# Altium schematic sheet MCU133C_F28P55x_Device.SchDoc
size 431 x 279 mm; Date: Not shown in title block; ApprovedBy: Not shown in title block; CheckedBy: Not shown in title block; Author: Not shown in title block; CompanyName: Not shown in title block; Engineer: Not shown in title block; Organization: Not shown in title block; Address1: Not shown in title block; Address2: Not shown in title block; Address3: Not shown in title block; Address4: Not shown in title block; DocumentNumber: 4; Revision: Use project parameter SCH_Rev; SheetNumber: 4; SheetTotal: 8; PageSetup: Record=PageOptions¦CenterHorizontal=True¦CenterVertical=True¦PrintScale=1.00¦XCorrection=1.00¦YCorrection=1.00¦PrintKind=0¦BorderSize=5000000¦LeftOffset=0¦BottomOffset=0¦Orientation=2¦PaperLength=1000¦PaperWidth=1000¦Scale=100¦PaperSource=15¦PrintQuality=600¦MediaType=1¦DitherType=10¦PaperKind=Letter¦PrintScaleMode=1
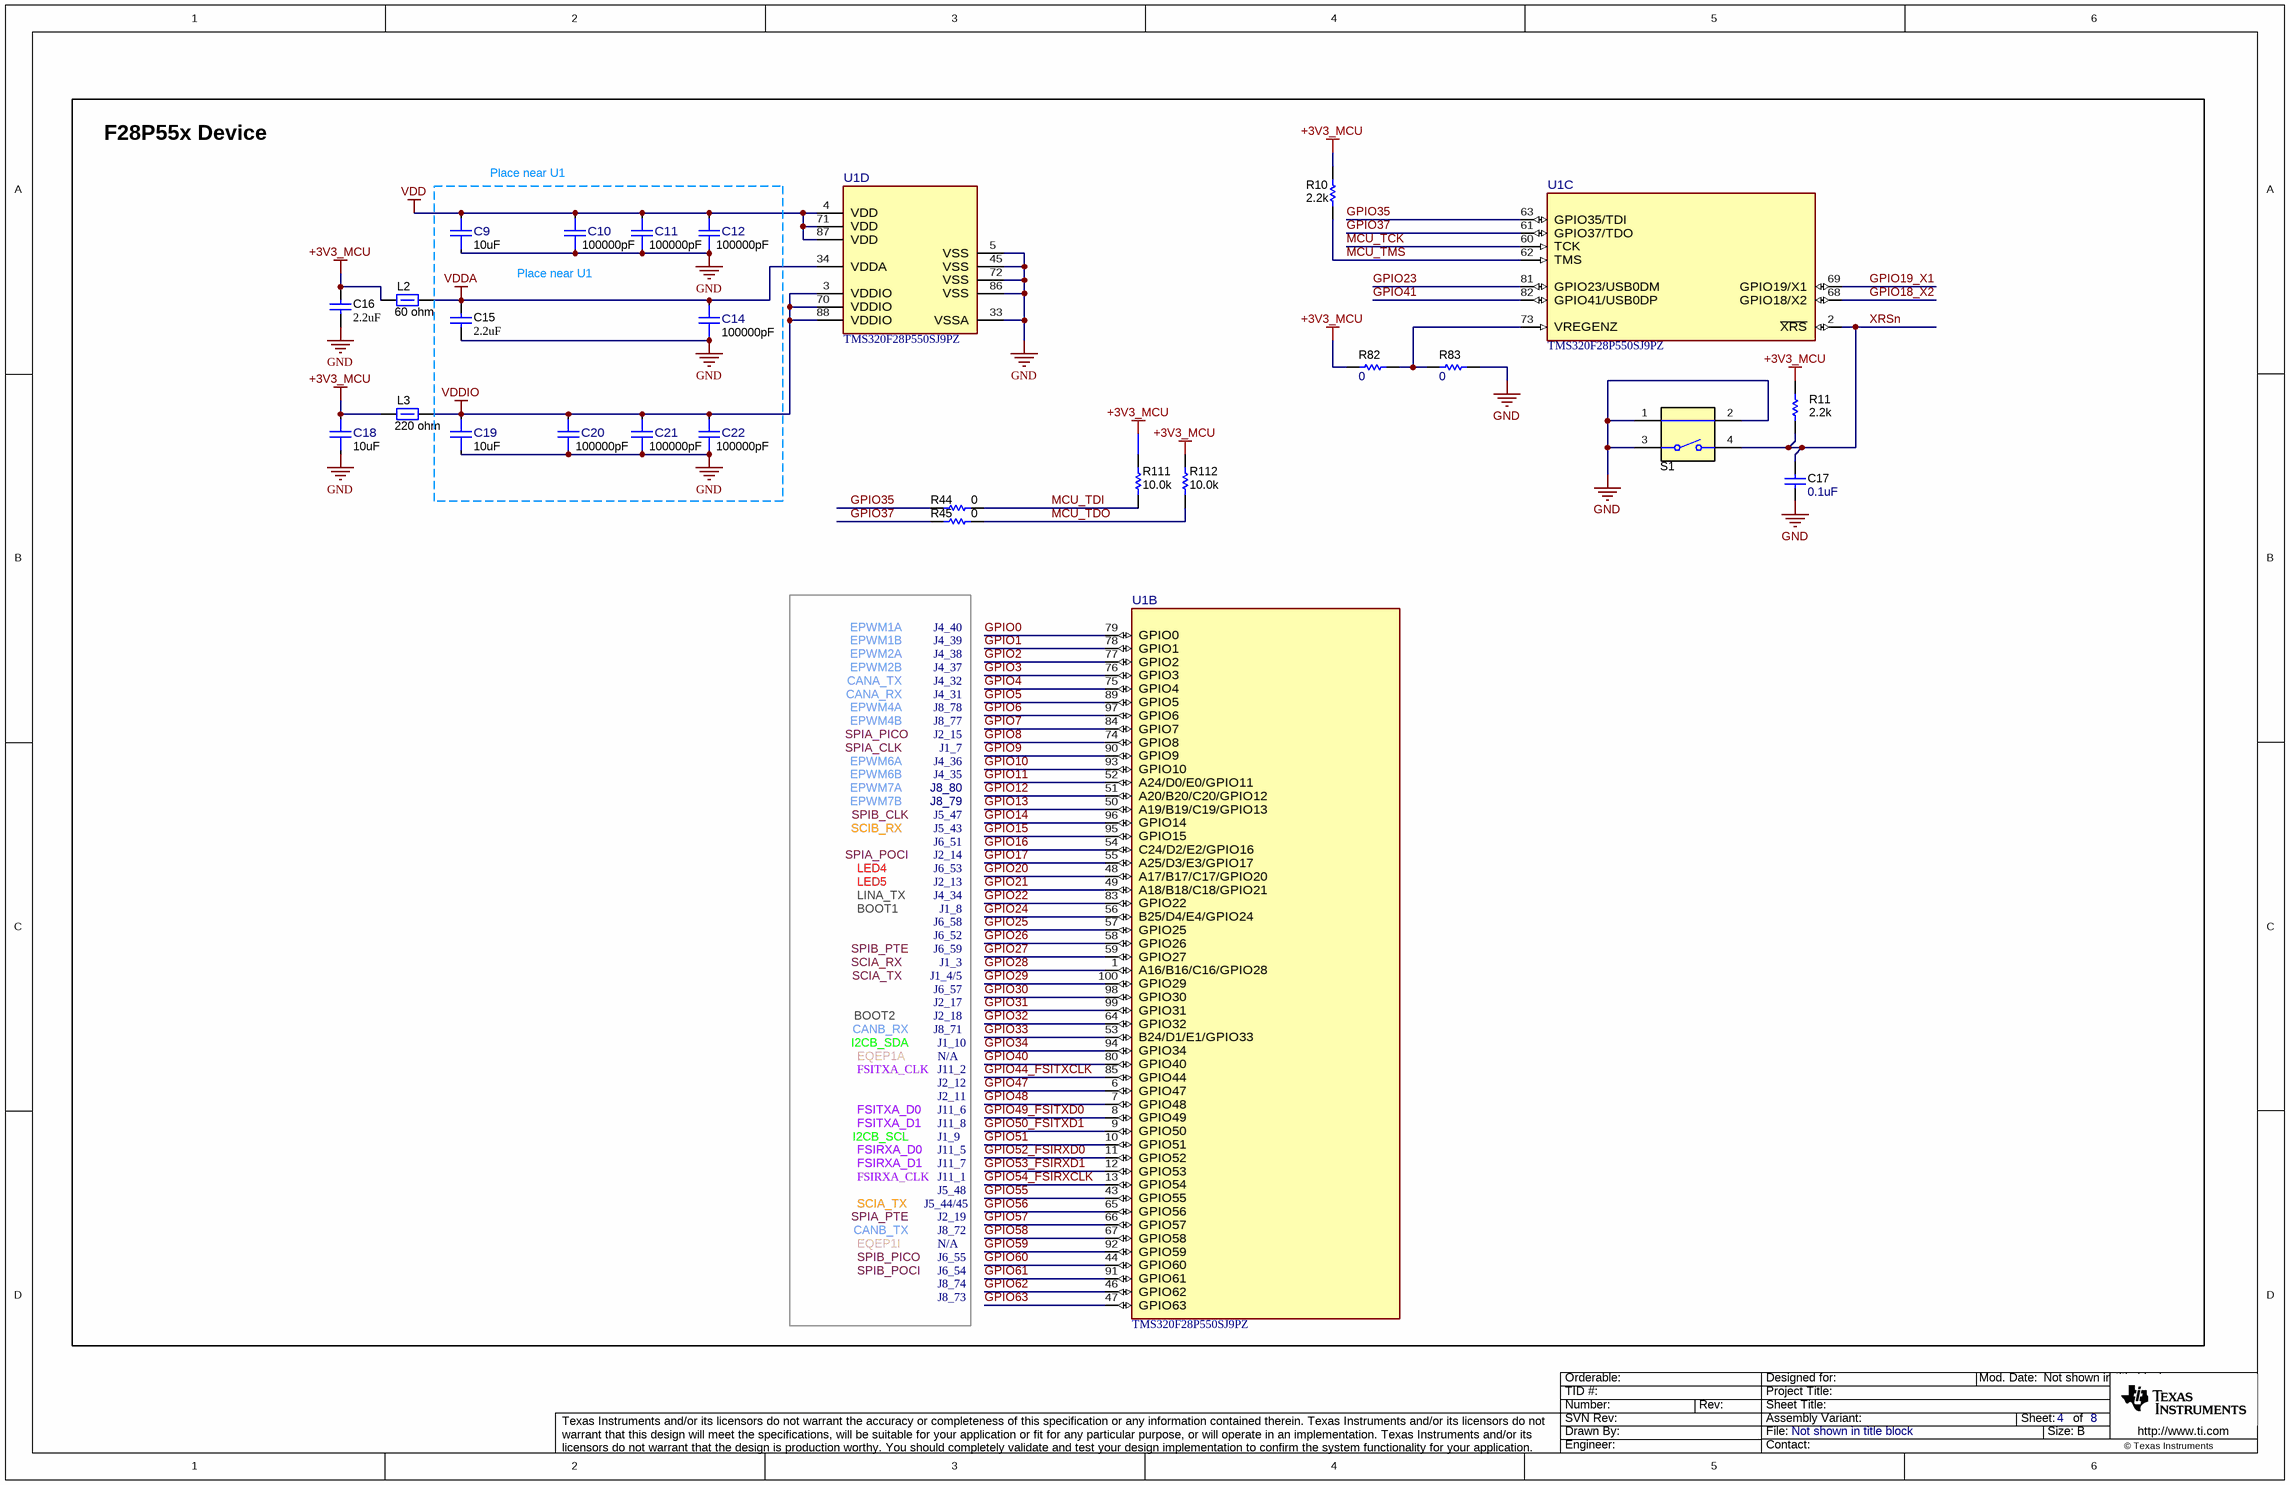
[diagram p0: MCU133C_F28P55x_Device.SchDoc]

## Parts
C9  ValueDisplayed: 10uF  [FP-CC0603KRX5R6BB106_0603-MFG]  (hidden comment: CC0603KRX5R6BB106)
C10  ValueDisplayed: 100000pF  [FP-885012205018_0402-MFG]  (hidden comment: 885012205018)
C11  ValueDisplayed: 100000pF  [FP-885012205018_0402-MFG]  (hidden comment: 885012205018)
C12  ValueDisplayed: 100000pF  [FP-885012205018_0402-MFG]  (hidden comment: 885012205018)
C14  ValueDisplayed: 100000pF  [FP-885012205018_0402-MFG]  (hidden comment: 885012205018)
C15  ValueDisplayed: 2.2uF  [0603]  (hidden comment: CGA3E3X5R1A225K080AB)
C16  ValueDisplayed: 2.2uF  [0603]  (hidden comment: CGA3E3X5R1A225K080AB)
C17  ValueDisplayed: 0.1uF  [0402]  (hidden comment: 885012205037)
C18  ValueDisplayed: 10uF  [FP-CC0603KRX5R6BB106_0603-MFG]  (hidden comment: CC0603KRX5R6BB106)
C19  ValueDisplayed: 10uF  [FP-CC0603KRX5R6BB106_0603-MFG]  (hidden comment: CC0603KRX5R6BB106)
C20  ValueDisplayed: 100000pF  [FP-885012205018_0402-MFG]  (hidden comment: 885012205018)
C21  ValueDisplayed: 100000pF  [FP-885012205018_0402-MFG]  (hidden comment: 885012205018)
C22  ValueDisplayed: 100000pF  [FP-885012205018_0402-MFG]  (hidden comment: 885012205018)
L2  value 60 ohm  [0805_HV]  (hidden comment: 742792063)
L3  ValueDisplayed: 220 ohm  [0805_HV]  (hidden comment: 742792022)
R10  ValueDisplayed: 2.2k  [0402]  (hidden comment: CRCW04022K20JNED)
R11  ValueDisplayed: 2.2k  [0402]  (hidden comment: CRCW04022K20JNED)
R44  ValueDisplayed: 0  [0402]  (hidden comment: RC0402JR-070RL)
R45  ValueDisplayed: 0  [0402]  (hidden comment: RC0402JR-070RL)
R82  ValueDisplayed: 0  [0402]  (hidden comment: ERJ-2GE0R00X)
R83  ValueDisplayed: 0  [0402]  (hidden comment: ERJ-2GE0R00X)
R111  ValueDisplayed: 10.0k  [0603]  (hidden comment: RC0603FR-0710KL)
R112  ValueDisplayed: 10.0k  [0603]  (hidden comment: RC0603FR-0710KL)
S1  1188E-1K2-V-TR  [SW_1188E]  (value not drawn)
U1  TMS320F28P550SJ9PZ  [PZ0100A-MFG]  (parts B,C,D of 4)

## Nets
+3V3_MCU: C16.1 C18.2 L2.1 L3.1 R10.2 R11.2 R82.1 R111.2 R112.2
GND: C9.1 C10.1 C11.1 C12.1 C14.1 C15.2 C16.2 C17.2 C18.1 C19.1 C20.1 C21.1 C22.1 R83.2 S1.1 S1.2 S1.3 U1.5(VSS) U1.33(VSSA) U1.45(VSS) U1.72(VSS) U1.86(VSS)
VDD: C9.2 C10.2 C11.2 C12.2 U1.4(VDD) U1.71(VDD) U1.87(VDD)
VDDA: C14.2 C15.1 L2.2 U1.34(VDDA)
VDDIO: C19.2 C20.2 C21.2 C22.2 L3.2 U1.3(VDDIO) U1.70(VDDIO) U1.88(VDDIO)
GPIO0: U1.79(GPIO0)
GPIO1: U1.78(GPIO1)
GPIO2: U1.77(GPIO2)
GPIO3: U1.76(GPIO3)
GPIO4: U1.75(GPIO4)
GPIO5: U1.89(GPIO5)
GPIO6: U1.97(GPIO6)
GPIO7: U1.84(GPIO7)
GPIO8: U1.74(GPIO8)
GPIO9: U1.90(GPIO9)
GPIO10: U1.93(GPIO10)
GPIO11: U1.52(A24/D0/E0/GPIO11)
GPIO12: U1.51(A20/B20/C20/GPIO12)
GPIO13: U1.50(A19/B19/C19/GPIO13)
GPIO14: U1.96(GPIO14)
GPIO15: U1.95(GPIO15)
GPIO16: U1.54(C24/D2/E2/GPIO16)
GPIO17: U1.55(A25/D3/E3/GPIO17)
GPIO18_X2: U1.68(GPIO18/X2)
GPIO19_X1: U1.69(GPIO19/X1)
GPIO20: U1.48(A17/B17/C17/GPIO20)
GPIO21: U1.49(A18/B18/C18/GPIO21)
GPIO22: U1.83(GPIO22)
GPIO23: U1.81(GPIO23/USB0DM)
GPIO24: U1.56(B25/D4/E4/GPIO24)
GPIO25: U1.57(GPIO25)
GPIO26: U1.58(GPIO26)
GPIO27: U1.59(GPIO27)
GPIO28: U1.1(A16/B16/C16/GPIO28)
GPIO29: U1.100(GPIO29)
GPIO30: U1.98(GPIO30)
GPIO31: U1.99(GPIO31)
GPIO32: U1.64(GPIO32)
GPIO33: U1.53(B24/D1/E1/GPIO33)
GPIO34: U1.94(GPIO34)
GPIO35: R44.1 U1.63(GPIO35/TDI)
GPIO37: R45.1 U1.61(GPIO37/TDO)
GPIO40: U1.80(GPIO40)
GPIO41: U1.82(GPIO41/USB0DP)
GPIO44_FSITXCLK: U1.85(GPIO44)
GPIO47: U1.6(GPIO47)
GPIO48: U1.7(GPIO48)
GPIO49_FSITXD0: U1.8(GPIO49)
GPIO50_FSITXD1: U1.9(GPIO50)
GPIO51: U1.10(GPIO51)
GPIO52_FSIRXD0: U1.11(GPIO52)
GPIO53_FSIRXD1: U1.12(GPIO53)
GPIO54_FSIRXCLK: U1.13(GPIO54)
GPIO55: U1.43(GPIO55)
GPIO56: U1.65(GPIO56)
GPIO57: U1.66(GPIO57)
GPIO58: U1.67(GPIO58)
GPIO59: U1.92(GPIO59)
GPIO60: U1.44(GPIO60)
GPIO61: U1.91(GPIO61)
GPIO62: U1.46(GPIO62)
GPIO63: U1.47(GPIO63)
MCU_TCK: U1.60(TCK)
MCU_TDI: R44.2 R111.1
MCU_TDO: R45.2 R112.1
MCU_TMS: R10.1 U1.62(TMS)
XRSn: C17.1 R11.1 S1.4 U1.2(~{XRS})
NetR82_2: R82.2 R83.1 U1.73(VREGENZ)

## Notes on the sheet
- F28P55x Device
- Place near U1
- (near C10) Place near U1
- EPWM1A
- J4_40
- CANA_TX
- CANA_RX
- EPWM1B
- EPWM2A
- EPWM2B
- J4_39
- J4_38
- J4_37
- J4_31
- J4_32
- SPIA_CLK
- EPWM6A
- EPWM4A
- EPWM4B
- SPIA_PICO
- J4_36
- J2_15
- J1_7
- J8_78
- J8_77
- SCIB_RX
- EPWM6B
- EPWM7A
- EPWM7B
- SPIB_CLK
- J4_35
- J5_43
- J8_80
- J5_47
- J8_79
- LINA_TX
- LED4
- LED5
- SPIA_POCI
- J4_34
- J6_51
- J2_14
- J6_53
- J2_13
- BOOT1
- SCIA_RX
- SPIB_PTE
- J6_58
- J6_52
- J6_59
- J1_8
- J1_3
- BOOT2
- SCIA_TX
- CANB_RX
- J1_4/5
- J6_57
- J2_17
- J2_18
- J8_71
- EQEP1A
- FSITXA_CLK
- I2CB_SDA
- J2_11
- J1_10
- N/A
- J2_12
- J11_2
- FSITXA_D0
- FSITXA_D1
- FSIRXA_D0
- FSIRXA_D1
- I2CB_SCL
- J11_8
- J1_9
- J11_6
- J11_5
- J11_7
- FSIRXA_CLK
- SPIA_PTE
- CANB_TX
- J5_44/45
- J2_19
- J5_48
- J11_1
- J8_72
- SPIB_POCI
- EQEP1I
- SPIB_PICO
- J6_55
- J6_54
- J8_74
- J8_73

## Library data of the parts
C9 C18 C19 = CMP-0092309-1: Cap Ceramic 10uF 10V X5R 10% SMD 0603 85C Paper T/R; Manufacturer: YAGEO; Cap_F: 10µF; TempCo: 15%; Category 7542B8484461Ae85: Passive Components; Category 4C11811B7D3097D6: Single Components; SizeZ_mm: 1mm; Category F8883582C9A8234F: Capacitors; AEC Qualified: No; Value: 10µF; Category 85Ce48C4B2B95E09: Uncategorized
C10-C12 C14 C20-C22 = CMP-0090362-1: 0.1µF ±10% 10V Ceramic Capacitor X7R 0402 (1005 Metric); Manufacturer: Wurth Electronics; AEC Qualified: No; Value: 100nF; SizeZ_mm: 0.55mm; TempCo: 15%
C15 C16 = CMP-0007091-1: CAP, CERM, 2.2 uF, 10 V, +/- 10%, X5R, AEC-Q200 Grade 3, 0603; Manufacturer: TDK; TaMin_C: -55°C; Polarized: N; SizeAreaWB_mm2: 4.68; Value1: Unknown; U/M: EA; Value: 2.2uF; TaMax_C: 85°C; SizeZ_mm: 1; SizeX_mm: 1.6; SizeY_mm: 0.8; Value2: 10V; SizeArea_mm2: 1.28; AEC Qualified: Y; Cap_F: 2.2µF; AEC Grade: 3; AEC Category: Q200
C17 = CMP-0006228-2: CAP, CERM, 0.1 uF, 16 V, +/- 10%, X7R, 0402; Manufacturer: Wurth Elektronik; TaMin_C: -55°C; Polarized: N; SizeAreaWB_mm2: 3; Value1: Unknown; U/M: EA; Value: 0.1uF; TaMax_C: 125°C; SizeZ_mm: 0.6; SizeX_mm: 1; SizeY_mm: 0.5; Value2: 16V; Cap_F: 100nF; AEC Category: Q200
L2 = CMP-0003093-1: Ferrite Bead, 60 ohm @ 100 MHz, 3 A, 0805; Manufacturer: Wurth Elektronik; Ztyp@1GHz_Ohm: 95.384; ZTyp@100MHz_Ohm: 60; SizeAreaWB_mm2: 6.75; DCR_ohm: 0.025; Value1: 0.025 ohm; Imax_A: 3A; SizeZ_mm: 1.45; SizeX_mm: 2; SizeY_mm: 1.25; SizeArea_mm2: 2.5
L3 = CMP-0003073-1: Ferrite Bead, 220 ohm @ 100 MHz, 2 A, 0805; Manufacturer: Wurth Elektronik; Ztyp@1GHz_Ohm: 190.289; ZTyp@100MHz_Ohm: 220; SizeAreaWB_mm2: 6.75; DCR_ohm: 0.05; Value1: 0.05 ohm; Value: 220 ohm; Imax_A: 2A; SizeZ_mm: 1.45; SizeX_mm: 2; SizeY_mm: 1.25; SizeArea_mm2: 2.5
R10 R11 = CMP-0026890-5: RES, 2.2 k, 5%, 0.063 W, AEC-Q200 Grade 0, 0402; Manufacturer: Vishay-Dale; Value: 2.2k; Value_Code: 2k20; Power_W: 63mW; Value2: 0.063W; VDC_V: 50V; TempCo: 200 ppm/C; EIA_Code: E24; AEC Category: Q200; AEC Qualified: Y; AEC Grade: 0; SizeArea_mm2: 0.5; SizeX_mm: 1; SizeZ_mm: 0.6
R44 R45 = CMP-0027004-2: RES, 0, 5%, 0.063 W, 0402; Manufacturer: Yageo America; Power_W: 63mW; TempCo: 200 ppm/C; Value_Code: 0000; U/M: EA; Value: 0; EIA_Code: E24; SizeX_mm: 1; SizeY_mm: 0.5; SizeZ_mm: 0.6; Value2: 0.063W; VDC_V: 50V; AEC Category: Q200
R82 R83 = CMP-0026992-3: RES, 0, 5%, 0.1 W, AEC-Q200 Grade 0, 0402; Manufacturer: Panasonic; Power_W: 100mW; TempCo: 600 ppm/C; Value_Code: 0000; Value: 0; EIA_Code: E24; SizeX_mm: 1; SizeY_mm: 0.5; SizeZ_mm: 0.6; Value2: 0.1W; AEC Qualified: Y; VDC_V: 50V; AEC Category: Q200; SizeAreaWB_mm2: 3
R111 R112 = CMP-0022746-5: RES, 10.0 k, 1%, 0.1 W, 0603; Manufacturer: Yageo; Power_W: 100mW; TempCo: 100 ppm/C; Value_Code: 10k0; Value: 10.0k; EIA_Code: E96; Res_ohm: 10k; SizeX_mm: 1.6; SizeY_mm: 0.8; SizeZ_mm: 1; Value2: 0.1W; SizeArea_mm2: 1.28; AEC Qualified: N; VDC_V: 75V; AEC Category: Q200; SizeAreaWB_mm2: 4.68
S1 = CMP-0002328-1: Switch, SPST, 0.05 A, 12 VDC, SMD; Manufacturer: Diptronics; SizeAreaWB_mm2: 53.9; SizeArea_mm2: 27.3; SizeX_mm: 7.8; SizeY_mm: 3.5; VDC_V: 12V; PositionCount: 1; CurrentRating_mA: 50A
U1 = CMP-0043282-2: Real-Time Microcontroller, LQFP100; Manufacturer: Texas Instruments; SizeZ_mm: 1.6mm; AEC Qualified: No; Core Architecture: C28x; Data Bus Width: 32bits; Frequency_Fixed: 150MHz; Interface: I2C,SPI,UART,CAN,USB,LIN,SCI,SMBus; Max Supply Voltage: 3.63V; Memory Size: 1088KBytes; Memory Type: FLASH; Min Supply Voltage: 2.8V; Number Of A/D Converters: 5; Number Of Adc Channels: 35; Number Of Cores: 1; Number Of I/Os: 43; Number Of I2C Channels: 2; Number Of Pwm Channels: 24; Number Of Timers/Counters: 3; Ram Size: 133KBytes; Standoff Height: 0.05mm; TaMax_C: +125°C; TaMin_C: -40°C; TJmax_C: +150°C; AEC Category: Q200; CompType: IC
